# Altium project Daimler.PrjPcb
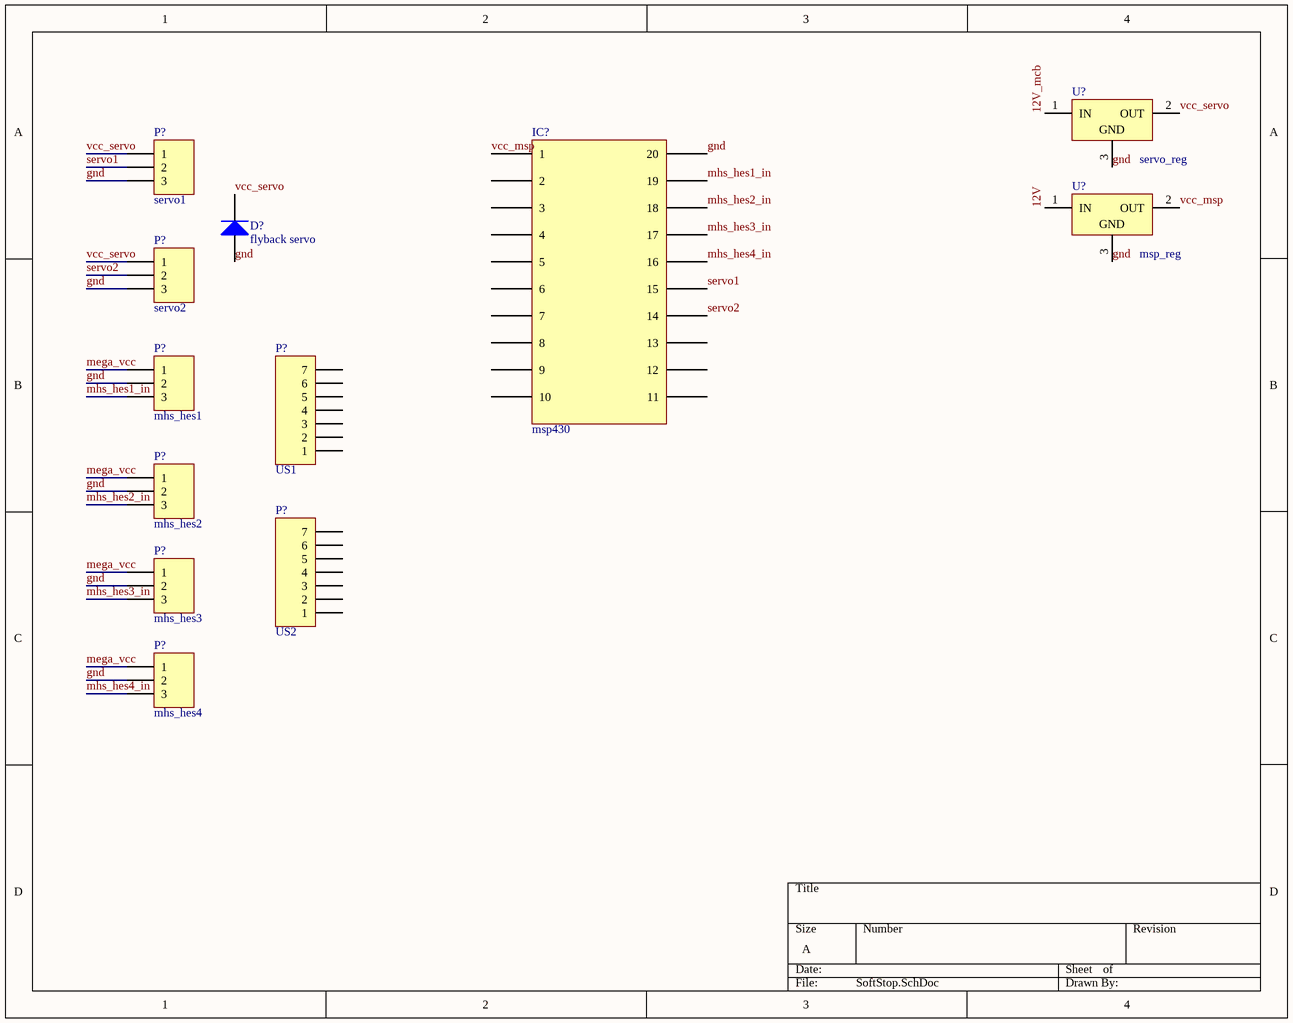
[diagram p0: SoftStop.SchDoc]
5 sheets, 47 parts. Net scope: global (net labels, ports and power ports of the same name join across sheets).
Sheets:
  SoftStop.SchDoc
  RPi.SchDoc
  HardStop.SchDoc
  Safety.SchDoc
  Navigation.SchDoc

## Sheet SoftStop.SchDoc
size A

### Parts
(Parts that share a designator on the sheet are numbered #1, #2 ... from top to bottom, then left to right.)
D?#1  flyback servo  [DO-41]
IC?#1  msp430  [msp430]
P?#1  servo1  [HDR1X3H]
P?#2  servo2  [HDR1X3H]
P?#3  mhs_hes1  [HDR1X3H]
P?#4  mhs_hes2  [HDR1X3H]
P?#5  US1  [HDR1X7H]
P?#6  mhs_hes3  [HDR1X3H]
P?#7  US2  [HDR1X7H]
P?#8  mhs_hes4  [HDR1X3H]
U?#1  servo_reg  [TO220ABN]
U?#2  msp_reg  [TO220ABN]

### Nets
12V: U?#2.1(IN)
12V_mcb: U?#1.1(IN)
gnd: D?#1.1(A) IC?#1.20 P?#1.3 P?#2.3 P?#3.2 P?#4.2 P?#6.2 P?#8.2 U?#1.3(GND) U?#2.3(GND)
mega_vcc: P?#3.1 P?#4.1 P?#6.1 P?#8.1
mhs_hes1_in: IC?#1.19 P?#3.3
mhs_hes2_in: IC?#1.18 P?#4.3
mhs_hes3_in: IC?#1.17 P?#6.3
mhs_hes4_in: IC?#1.16 P?#8.3
servo1: IC?#1.15 P?#1.2
servo2: IC?#1.14 P?#2.2
vcc_msp: IC?#1.1 U?#2.2(OUT)
vcc_servo: D?#1.2(K) P?#1.1 P?#2.1 U?#1.2(OUT)

Not connected (* = marked no-connect by the designer): IC?#1 2 3 4 5 6 7 8 9 10 11 12 13; P?#5 1 2 3 4 5 6 7; P?#7 1 2 3 4 5 6 7

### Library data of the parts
D?#1 = Diode 1N4001: 1 Amp General Purpose Rectifier
P?#1-P?#4 P?#6 P?#8 = Header 3H: Header, 3-Pin, Right Angle
P?#5 P?#7 = Header 7H: Header, 7-Pin, Right Angle
U?#1 U?#2 = L7805CV: Positive Voltage Regulator; Note: Tab is connected to pin 3 (GND).

## Sheet RPi.SchDoc
size A
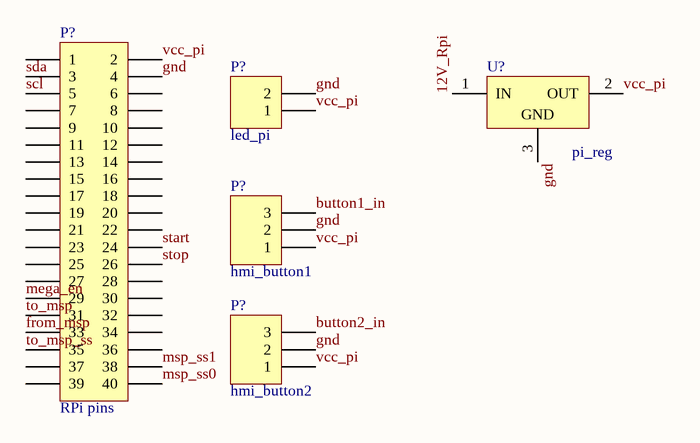
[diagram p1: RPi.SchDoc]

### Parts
(Parts that share a designator on the sheet are numbered #1, #2 ... from top to bottom, then left to right.)
P?#9  RPi pins  [HDR2X20]
P?#10  led_pi  [HDR1X2H]
P?#11  hmi_button1  [HDR1X3H]
P?#12  hmi_button2  [HDR1X3H]
U?#3  pi_reg  [TO220ABN]

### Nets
12V_Rpi: U?#3.1(IN)
button1_in: P?#11.3
button2_in: P?#12.3
from_msp: P?#9.33
gnd: P?#9.4 P?#10.2 P?#11.2 P?#12.2 U?#3.3(GND)
mega_en: P?#9.29
msp_ss0: P?#9.40
msp_ss1: P?#9.38
scl: P?#9.5
sda: P?#9.3
start: P?#9.24
stop: P?#9.26
to_msp: P?#9.31
to_msp_ss: P?#9.35
vcc_pi: P?#9.2 P?#10.1 P?#11.1 P?#12.1 U?#3.2(OUT)

Not connected (* = marked no-connect by the designer): P?#9 1 6 7 8 9 10 11 12 13 14 15 16 17 18 19 20 21 22 23 25 27 28 30 32 34 36 37 39

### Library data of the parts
P?#9 = Header 20X2: Header, 20-Pin, Dual row
P?#10 = Header 2H: Header, 2-Pin, Right Angle
P?#11 P?#12 = Header 3H: Header, 3-Pin, Right Angle
U?#3 = L7805CV: as U?#1 on sheet SoftStop

## Sheet HardStop.SchDoc
size A
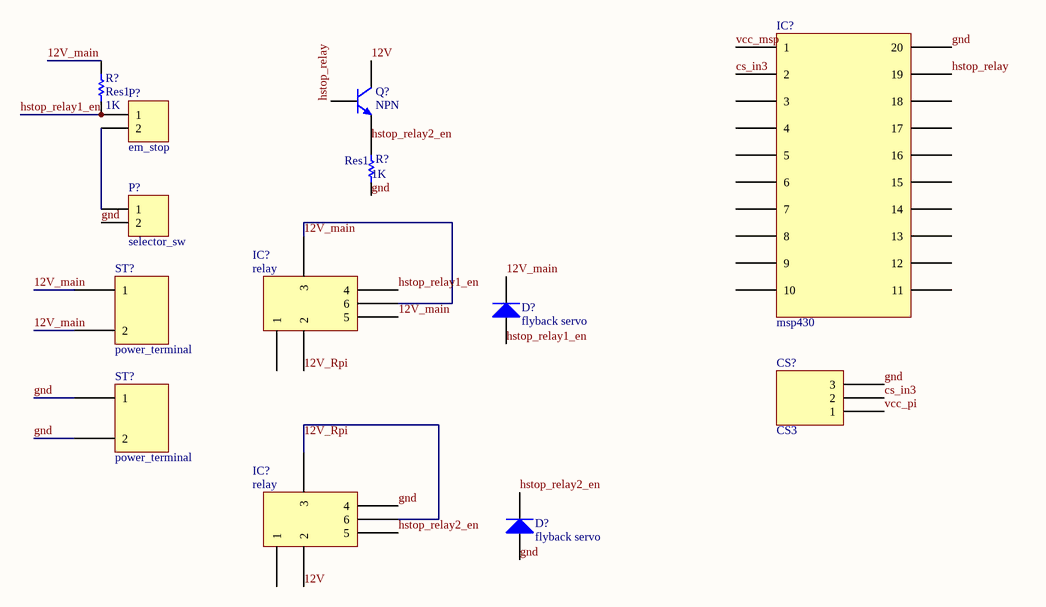
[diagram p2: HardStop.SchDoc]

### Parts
(Parts that share a designator on the sheet are numbered #1, #2 ... from top to bottom, then left to right.)
CS?#1  CS3  [ACS712]
D?#2  flyback servo  [DO-41]
D?#3  flyback servo  [DO-41]
IC?#2  msp430  [msp430]
IC?#3  relay  [relay JQX 15F]
IC?#4  relay  [relay JQX 15F]
P?#13  em_stop  [HDR1X2H]
P?#14  selector_sw  [HDR1X2H]
Q?#1  NPN  [TO-226-AA]
R?#1  Res1  value 1K  [AXIAL-0.3]
R?#2  Res1  value 1K  [AXIAL-0.3]
ST?#1  power_terminal  [screw_terminal_5]
ST?#2  power_terminal  [screw_terminal_5]

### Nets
12V: IC?#4.2 Q?#1.1(C)
12V_main: D?#2.2(K) IC?#3.3 IC?#3.5 IC?#3.6 R?#1.2 ST?#1.1 ST?#1.2
12V_Rpi: IC?#3.2 IC?#4.3 IC?#4.6
cs_in3: CS?#1.2 IC?#2.2
gnd: CS?#1.3 D?#3.1(A) IC?#2.20 IC?#4.4 P?#14.2 R?#2.1 ST?#2.1 ST?#2.2
hstop_relay: IC?#2.19 Q?#1.2(B)
hstop_relay1_en: D?#2.1(A) IC?#3.4 P?#13.1 R?#1.1
hstop_relay2_en: D?#3.2(K) IC?#4.5 Q?#1.3(E) R?#2.2
vcc_msp: IC?#2.1
vcc_pi: CS?#1.1
NetP?#13_2: P?#13.2 P?#14.1

Not connected (* = marked no-connect by the designer): IC?#2 3 4 5 6 7 8 9 10 11 12 13 14 15 16 17 18; IC?#3 1; IC?#4 1

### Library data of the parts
CS?#1 = ACS712
D?#2 D?#3 = Diode 1N4001: 1 Amp General Purpose Rectifier
IC?#3 IC?#4 = relay JQX-15F
P?#13 P?#14 = Header 2H: Header, 2-Pin, Right Angle
Q?#1 = NPN: NPN Bipolar Transistor
R?#1 R?#2 = Res1: Resistor
ST?#1 ST?#2 = screw_terminal

## Sheet Safety.SchDoc
size A
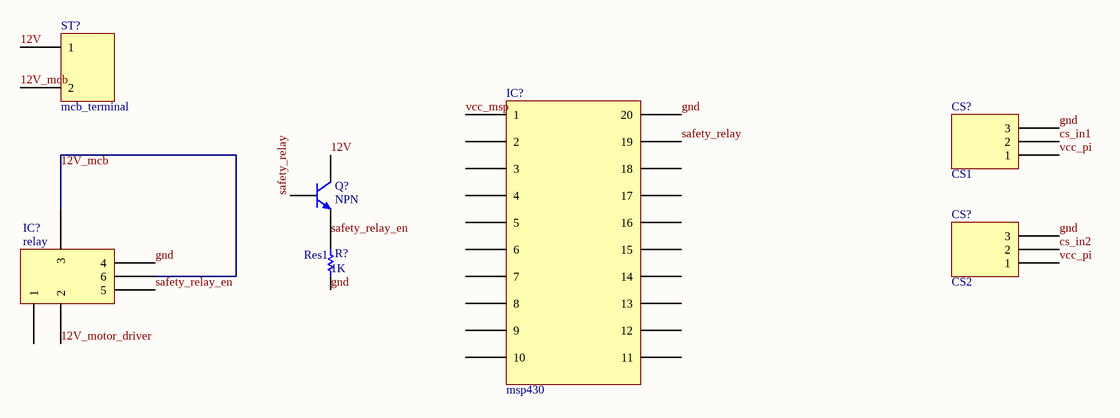
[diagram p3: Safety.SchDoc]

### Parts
(Parts that share a designator on the sheet are numbered #1, #2 ... from top to bottom, then left to right.)
CS?#2  CS1  [ACS712]
CS?#3  CS2  [ACS712]
IC?#5  msp430  [msp430]
IC?#6  relay  [relay JQX 15F]
Q?#2  NPN  [TO-226-AA]
R?#3  Res1  value 1K  [AXIAL-0.3]
ST?#3  mcb_terminal  [screw_terminal_5]

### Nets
12V: Q?#2.1(C) ST?#3.1
12V_mcb: IC?#6.3 IC?#6.6 ST?#3.2
12V_motor_driver: IC?#6.2
cs_in1: CS?#2.2
cs_in2: CS?#3.2
gnd: CS?#2.3 CS?#3.3 IC?#5.20 IC?#6.4 R?#3.1
safety_relay: IC?#5.19 Q?#2.2(B)
safety_relay_en: IC?#6.5 Q?#2.3(E) R?#3.2
vcc_msp: IC?#5.1
vcc_pi: CS?#2.1 CS?#3.1

Not connected (* = marked no-connect by the designer): IC?#5 2 3 4 5 6 7 8 9 10 11 12 13 14 15 16 17 18; IC?#6 1

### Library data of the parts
CS?#2 CS?#3 = ACS712
IC?#6 = relay JQX-15F
Q?#2 = NPN: NPN Bipolar Transistor
R?#3 = Res1: Resistor
ST?#3 = screw_terminal

## Sheet Navigation.SchDoc
size A
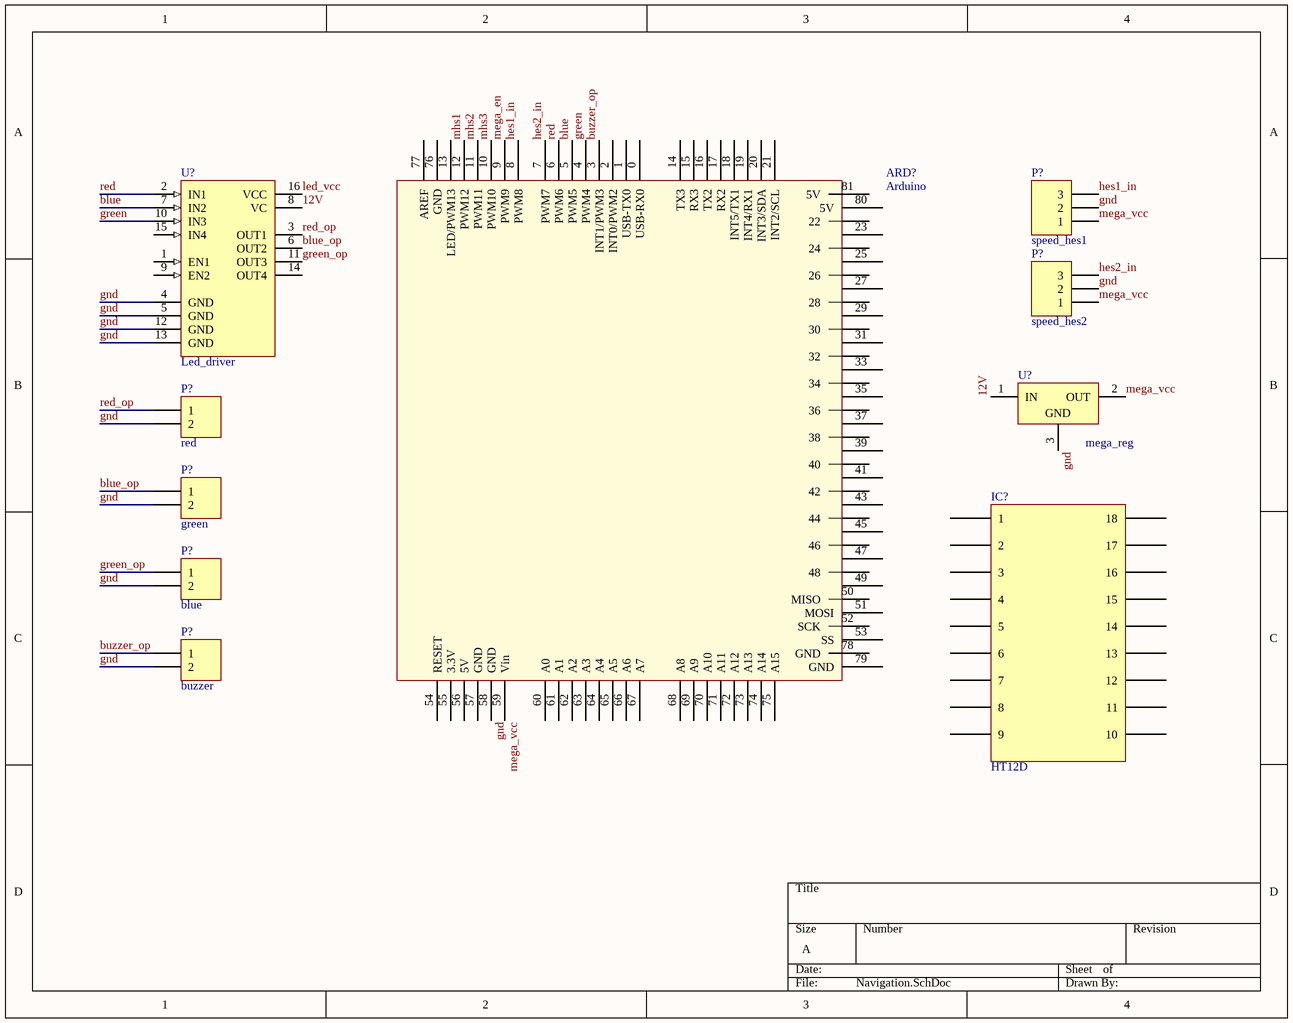
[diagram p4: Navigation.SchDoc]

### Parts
(Parts that share a designator on the sheet are numbered #1, #2 ... from top to bottom, then left to right.)
ARD?  Arduino  [Arduino]
IC?#7  HT12D  [HT12D]
P?#15  speed_hes1  [HDR1X3H]
P?#16  speed_hes2  [HDR1X3H]
P?#17  red  [HDR1X2H]
P?#18  green  [HDR1X2H]
P?#19  blue  [HDR1X2H]
P?#20  buzzer  [HDR1X2H]
U?#4  Led_driver  [DIP16]
U?#5  mega_reg  [TO220ABN]

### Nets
12V: U?#4.8(VC) U?#5.1(IN)
blue: ARD?.5(PWM5) U?#4.7(IN2)
blue_op: P?#18.1 U?#4.6(OUT2)
buzzer_op: ARD?.3(INT1/PWM3) P?#20.1
gnd: ARD?.58(GND) P?#15.2 P?#16.2 P?#17.2 P?#18.2 P?#19.2 P?#20.2 U?#4.4(GND) U?#4.5(GND) U?#4.12(GND) U?#4.13(GND) U?#5.3(GND)
green: ARD?.4(PWM4) U?#4.10(IN3)
green_op: P?#19.1 U?#4.11(OUT3)
hes1_in: ARD?.8(PWM8) P?#15.3
hes2_in: ARD?.7(PWM7) P?#16.3
led_vcc: U?#4.16(VCC)
mega_en: ARD?.9(PWM9)
mega_vcc: ARD?.59(Vin) P?#15.1 P?#16.1 U?#5.2(OUT)
mhs1: ARD?.12(PWM12)
mhs2: ARD?.11(PWM11)
mhs3: ARD?.10(PWM10)
red: ARD?.6(PWM6) U?#4.2(IN1)
red_op: P?#17.1 U?#4.3(OUT1)

Not connected (* = marked no-connect by the designer): ARD? 0(USB-RX0) 1(USB-TX0) 2(INT0/PWM2) 13(LED/PWM13) 14(TX3) 15(RX3) 16(TX2) 17(RX2) 18(INT5/TX1) 19(INT4/RX1) 20(INT3/SDA) 21(INT2/SCL) 22 23 24 25 26 27 28 29 30 31 32 33 34 35 36 37 38 39 40 41 42 43 44 45 46 47 48 49 50(MISO) 51(MOSI) 52(SCK) 53(SS) 54(RESET) 55(3.3V) 56(5V) 57(GND) 60(A0) 61(A1) 62(A2) 63(A3) 64(A4) 65(A5) 66(A6) 67(A7) 68(A8) 69(A9) 70(A10) 71(A11) 72(A12) 73(A13) 74(A14) 75(A15) 76(GND) 77(AREF) 78(GND) 79(GND) 80(5V) 81(5V); IC?#7 1 2 3 4 5 6 7 8 9 10 11 12 13 14 15 16 17 18; U?#4 1(EN1) 9(EN2) 14(OUT4) 15(IN4)

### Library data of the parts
P?#15 P?#16 = Header 3H: Header, 3-Pin, Right Angle
P?#17-P?#20 = Header 2H: Header, 2-Pin, Right Angle
U?#4 = L293D: Push-Pull Four Channel Driver With Diode
U?#5 = L7805CV: as U?#1 on sheet SoftStop

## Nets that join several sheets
12V: SoftStop (U?#2.1), HardStop (IC?#4.2 Q?#1.1), Safety (Q?#2.1 ST?#3.1), Navigation (U?#4.8 U?#5.1)
12V_mcb: SoftStop (U?#1.1), Safety (IC?#6.3 IC?#6.6 ST?#3.2)
12V_Rpi: RPi (U?#3.1), HardStop (IC?#3.2 IC?#4.3 IC?#4.6)
gnd: SoftStop (10 pins), RPi (5 pins), HardStop (8 pins), Safety (5 pins), Navigation (12 pins)
mega_en: RPi (P?#9.29), Navigation (ARD?.9)
mega_vcc: SoftStop (P?#3.1 P?#4.1 P?#6.1 P?#8.1), Navigation (ARD?.59 P?#15.1 P?#16.1 U?#5.2)
vcc_msp: SoftStop (IC?#1.1 U?#2.2), HardStop (IC?#2.1), Safety (IC?#5.1)
vcc_pi: RPi (5 pins), HardStop (CS?#1.1), Safety (CS?#2.1 CS?#3.1)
